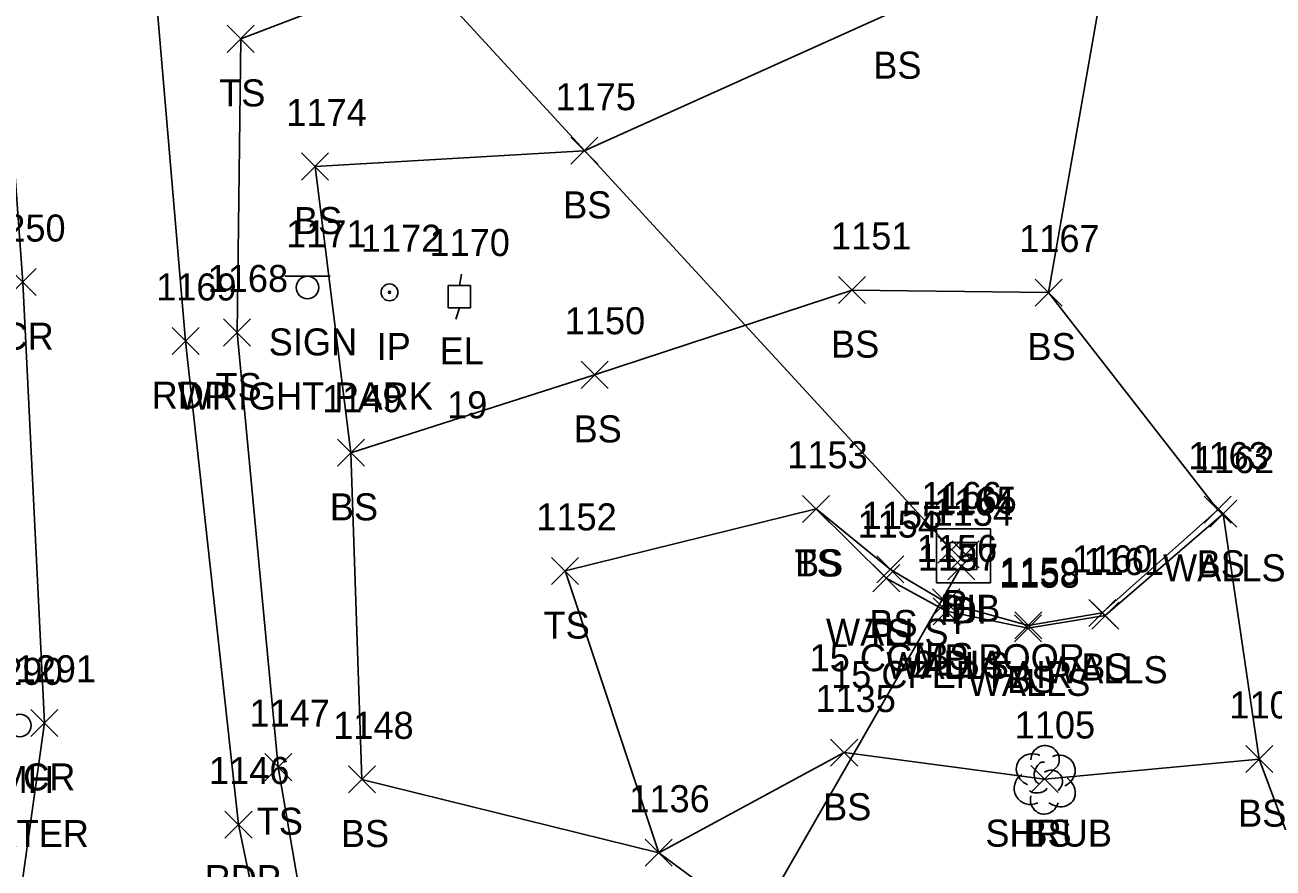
# Model space of a CAD drawing. Extents: x 1461855 to 1464118, y 556196 to 557441.
# Drawn here: x 1462417.3 to 1462509.6, y 556442 to 556504.3 of the extents above; entities that cross this region are included whole.
import ezdxf

# ---------------------------------------------------------------- set-up
doc = ezdxf.new("R2010")
doc.units = 0
for name, color, linetype in [('D_A', 7, 'Continuous'), ('D_C', 7, 'Continuous'), ('D_I', 7, 'Continuous'), ('D_TIC', 7, 'Continuous'), ('DCP', 7, 'Continuous'), ('DS', 7, 'Continuous'), ('L_A', 7, 'Continuous'), ('L_I', 7, 'Continuous'), ('L_TIC', 7, 'Continuous'), ('LELB', 7, 'Continuous'), ('LSH', 7, 'Continuous'), ('LSOGP', 7, 'Continuous'), ('LWS', 7, 'Continuous'), ('M_A', 7, 'Continuous'), ('M_I', 7, 'Continuous'), ('MPIR', 7, 'Continuous'), ('P_A', 7, 'Continuous'), ('P_I', 7, 'Continuous'), ('P_TIC', 7, 'Continuous'), ('PET', 7, 'Continuous'), ('PRC', 7, 'Continuous'), ('S_A', 7, 'Continuous'), ('S_C', 7, 'Continuous'), ('S_I', 7, 'Continuous'), ('SSGN', 7, 'Continuous'), ('U_A', 7, 'Continuous'), ('U_C', 7, 'Continuous'), ('U_I', 7, 'Continuous'), ('UEPT', 7, 'Continuous'), ('UUMH', 7, 'Continuous')]:
    doc.layers.add(name, color=color, linetype=linetype)

msp = doc.modelspace()

# ---------------------------------------------------------------- linework, layer by layer
at = {"layer": 'D_TIC'}
for points in [[(1462484.784, 556464.552), (1462486.784, 556466.552)], [(1462486.784, 556464.552), (1462484.784, 556466.552)], [(1462485.833, 556464.207), (1462487.833, 556466.207)], [(1462487.833, 556464.207), (1462485.833, 556466.207)], [(1462485.51, 556463.306), (1462487.51, 556465.306)], [(1462487.51, 556463.306), (1462485.51, 556465.306)]]:
    msp.add_lwpolyline(points, dxfattribs=at)
at = {"layer": 'DCP'}
for points in [[(1462485.784, 556465.552), (1462401.016, 556557.727)], [(1462451.827, 556403.885), (1462486.51, 556464.306)]]:
    msp.add_lwpolyline(points, dxfattribs=at)
at = {"layer": 'DS'}
for p, q in [((1462484.67, 556467.079), (1462488.67, 556467.079)), ((1462484.67, 556463.079), (1462484.67, 556467.079)), ((1462488.67, 556467.079), (1462488.67, 556463.079)), ((1462485.67, 556464.079), (1462485.67, 556466.079)), ((1462485.67, 556466.079), (1462487.67, 556466.079)), ((1462487.67, 556466.079), (1462487.67, 556464.079)), ((1462486.675, 556465.081), (1462486.675, 556465.081)), ((1462486.675, 556465.081), (1462486.675, 556465.081)), ((1462487.67, 556464.079), (1462485.67, 556464.079)), ((1462488.67, 556463.079), (1462484.67, 556463.079))]:
    msp.add_line(p, q, dxfattribs=at)
at = {"layer": 'L_TIC'}
for points in [[(1462432.214, 556502.32), (1462434.214, 556504.32)], [(1462434.214, 556502.32), (1462432.214, 556504.32)], [(1462457.622, 556494.039), (1462459.622, 556496.039)], [(1462459.622, 556494.039), (1462457.622, 556496.039)], [(1462437.718, 556492.877), (1462439.718, 556494.877)], [(1462439.718, 556492.877), (1462437.718, 556494.877)], [(1462477.434, 556483.742), (1462479.434, 556485.742)], [(1462479.434, 556483.742), (1462477.434, 556485.742)], [(1462491.963, 556483.557), (1462493.963, 556485.557)], [(1462493.963, 556483.557), (1462491.963, 556485.557)], [(1462431.945, 556480.601), (1462433.945, 556482.601)], [(1462433.945, 556480.601), (1462431.945, 556482.601)], [(1462458.394, 556477.473), (1462460.394, 556479.473)], [(1462460.394, 556477.473), (1462458.394, 556479.473)], [(1462440.368, 556471.708), (1462442.368, 556473.708)], [(1462442.368, 556471.708), (1462440.368, 556473.708)], [(1462440.368, 556471.708), (1462442.368, 556473.708)], [(1462442.368, 556471.708), (1462440.368, 556473.708)], [(1462474.768, 556467.56), (1462476.768, 556469.56)], [(1462476.768, 556467.56), (1462474.768, 556469.56)], [(1462474.768, 556467.56), (1462476.768, 556469.56)], [(1462476.768, 556467.56), (1462474.768, 556469.56)], [(1462504.472, 556467.494), (1462506.472, 556469.494)], [(1462506.472, 556467.494), (1462504.472, 556469.494)], [(1462504.882, 556467.202), (1462506.882, 556469.202)], [(1462506.882, 556467.202), (1462504.882, 556469.202)], [(1462456.204, 556462.965), (1462458.204, 556464.965)], [(1462458.204, 556462.965), (1462456.204, 556464.965)], [(1462480.271, 556463.082), (1462482.271, 556465.082)], [(1462482.271, 556463.082), (1462480.271, 556465.082)], [(1462479.956, 556462.433), (1462481.956, 556464.433)], [(1462481.956, 556462.433), (1462479.956, 556464.433)], [(1462479.956, 556462.433), (1462481.956, 556464.433)], [(1462481.956, 556462.433), (1462479.956, 556464.433)], [(1462484.391, 556460.638), (1462486.391, 556462.638)], [(1462486.391, 556460.638), (1462484.391, 556462.638)], [(1462484.417, 556459.986), (1462486.417, 556461.986)], [(1462486.417, 556459.986), (1462484.417, 556461.986)], [(1462495.939, 556459.865), (1462497.939, 556461.865)], [(1462497.939, 556459.865), (1462495.939, 556461.865)], [(1462490.459, 556458.944), (1462492.459, 556460.944)], [(1462492.459, 556458.944), (1462490.459, 556460.944)], [(1462496.158, 556459.665), (1462498.158, 556461.665)], [(1462498.158, 556459.665), (1462496.158, 556461.665)], [(1462490.442, 556458.729), (1462492.442, 556460.729)], [(1462492.442, 556458.729), (1462490.442, 556460.729)], [(1462476.846, 556449.533), (1462478.846, 556451.533)], [(1462478.846, 556449.533), (1462476.846, 556451.533)], [(1462507.542, 556449.057), (1462509.542, 556451.057)], [(1462509.542, 556449.057), (1462507.542, 556451.057)], [(1462434.991, 556448.457), (1462436.991, 556450.457)], [(1462436.991, 556448.457), (1462434.991, 556450.457)], [(1462441.185, 556447.55), (1462443.185, 556449.55)], [(1462443.185, 556447.55), (1462441.185, 556449.55)], [(1462441.185, 556447.55), (1462443.185, 556449.55)], [(1462443.185, 556447.55), (1462441.185, 556449.55)], [(1462491.661, 556447.578), (1462493.661, 556449.578)], [(1462493.661, 556447.578), (1462491.661, 556449.578)], [(1462463.138, 556442.125), (1462465.138, 556444.125)], [(1462465.138, 556442.125), (1462463.138, 556444.125)], [(1462463.138, 556442.125), (1462465.138, 556444.125)], [(1462465.138, 556442.125), (1462463.138, 556444.125)]]:
    msp.add_lwpolyline(points, dxfattribs=at)
at = {"layer": 'LELB'}
for points in [[(1462439.15, 556431.127), (1462435.991, 556449.457), (1462432.945, 556481.601), (1462433.214, 556503.32), (1462454.223, 556511.365), (1462474.435, 556520.417), (1462493.382, 556525.455)], [(1462442.185, 556448.55), (1462441.368, 556472.708), (1462438.718, 556493.877), (1462458.622, 556495.039), (1462481.557, 556505.37), (1462497.969, 556513.067)], [(1462441.368, 556472.708), (1462459.394, 556478.473), (1462478.434, 556484.742), (1462492.963, 556484.557)], [(1462511.588, 556441.871), (1462496.726, 556434.616), (1462482.019, 556429.925), (1462464.138, 556443.125), (1462457.204, 556463.965), (1462475.768, 556468.56), (1462480.956, 556463.433)], [(1462475.768, 556468.56), (1462481.271, 556464.082), (1462485.391, 556461.638), (1462491.459, 556459.944), (1462496.939, 556460.865), (1462505.472, 556468.494)], [(1462508.542, 556450.057), (1462492.661, 556448.578), (1462477.846, 556450.533), (1462464.138, 556443.125), (1462442.185, 556448.55)]]:
    msp.add_lwpolyline(points, dxfattribs=at)
at = {"layer": 'LSH'}
msp.add_line((1462492.661, 556448.578), (1462492.661, 556448.578), dxfattribs=at)
msp.add_line((1462492.661, 556448.578), (1462492.661, 556448.578), dxfattribs=at)
msp.add_arc((1462492.707, 556450.011), 1.047, 335.52715, 180.95627, dxfattribs=at)
for centre, major_axis, ratio, start_param, end_param in [((1462491.869, 556449.244), (1.21, -0.512), 0.895232, 1.570796, 4.712389), ((1462492.452, 556449.036), (-0.208, -0.792), 0.645439, 3.141593, 6.283185), ((1462493.702, 556449.161), (-1.141, -0.483), 0.949671, 1.570796, 4.712389), ((1462491.577, 556447.869), (0.584, -1.042), 0.959034, 3.141593, 6.283185), ((1462493.161, 556448.411), (-0.5, 0.667), 0.989748, 3.141593, 6.283185), ((1462492.202, 556447.827), (-0.625, -0.083), 0.423636, 0, 3.141593), ((1462493.661, 556447.744), (-1.09, 0.792), 0.841452, 1.570796, 4.712389), ((1462492.661, 556447.078), (0.265, 1.061), 0.942809, 1.570796, 4.712389)]:
    msp.add_ellipse(centre, major_axis=major_axis, ratio=ratio, start_param=start_param, end_param=end_param, dxfattribs=at)
at = {"layer": 'LSOGP'}
msp.add_lwpolyline([(1462563.174, 556376.777), (1462561.339, 556379.019), (1462559.886, 556380.724), (1462547.912, 556393.804), (1462536.148, 556406.17), (1462534.091, 556416.372), (1462526.144, 556425.112), (1462519.567, 556432.393), (1462517.78, 556434.532), (1462511.588, 556441.871), (1462508.542, 556450.057), (1462505.882, 556468.202), (1462505.472, 556468.494), (1462492.963, 556484.557), (1462497.969, 556513.067)], dxfattribs=at)
at = {"layer": 'LWS'}
msp.add_lwpolyline([(1462480.956, 556463.433), (1462485.417, 556460.986), (1462491.442, 556459.729), (1462497.158, 556460.665), (1462505.882, 556468.202)], dxfattribs=at)
at = {"layer": 'MPIR'}
for radius in [0.625, 0.0833]:
    msp.add_circle((1462444.222, 556484.572), radius, dxfattribs=at)
at = {"layer": 'P_TIC'}
for points in [[(1462416.096, 556484.328), (1462418.096, 556486.328)], [(1462418.096, 556484.328), (1462416.096, 556486.328)], [(1462428.146, 556479.97), (1462430.146, 556481.97)], [(1462430.146, 556479.97), (1462428.146, 556481.97)], [(1462417.694, 556451.734), (1462419.694, 556453.734)], [(1462419.694, 556451.734), (1462417.694, 556453.734)], [(1462432.054, 556444.214), (1462434.054, 556446.214)], [(1462434.054, 556444.214), (1462432.054, 556446.214)]]:
    msp.add_lwpolyline(points, dxfattribs=at)
at = {"layer": 'PET'}
msp.add_lwpolyline([(1462450.002, 556394.495), (1462444.864, 556401.11), (1462442.305, 556410.091), (1462435.592, 556433.018), (1462433.054, 556445.214), (1462429.146, 556480.97), (1462426.421, 556512.859), (1462424.327, 556541.511), (1462422.907, 556563.514), (1462420.115, 556594.818)], dxfattribs=at)
at = {"layer": 'PRC'}
msp.add_lwpolyline([(1462408.918, 556592.161), (1462412.204, 556557.563), (1462413.993, 556527.838), (1462417.096, 556485.328), (1462418.694, 556452.734), (1462415.654, 556430.869), (1462414.08, 556417.651)], dxfattribs=at)
at = {"layer": 'SSGN'}
for p, q in [((1462436.504, 556485.758), (1462439.838, 556485.758)), ((1462438.151, 556484.925), (1462438.151, 556484.925))]:
    msp.add_line(p, q, dxfattribs=at)
msp.add_circle((1462438.151, 556484.925), 0.833, dxfattribs=at)
at = {"layer": 'UEPT'}
for p, q in [((1462449.553, 556485.921), (1462449.386, 556485.088)), ((1462448.553, 556483.421), (1462448.553, 556485.088)), ((1462448.553, 556485.088), (1462450.22, 556485.088)), ((1462450.22, 556485.088), (1462450.22, 556483.421)), ((1462449.386, 556484.254), (1462449.386, 556484.254)), ((1462450.22, 556483.421), (1462448.553, 556483.421)), ((1462449.136, 556482.588), (1462449.386, 556483.421))]:
    msp.add_line(p, q, dxfattribs=at)
at = {"layer": 'UUMH'}
msp.add_line((1462417.712, 556452.544), (1462417.712, 556452.544), dxfattribs=at)
msp.add_circle((1462416.878, 556452.544), 0.833, dxfattribs=at)

# ---------------------------------------------------------------- texts
at = {"layer": 'D_A'}
for s, p in [('DIB', (1462484.936, 556460.207)), ('P', (1462485.162, 556460.552)), ('DI', (1462485.731, 556460.081)), ('P', (1462485.888, 556459.306))]:
    msp.add_text(s, height=2, dxfattribs=at).set_placement(p)
at = {"layer": 'D_C'}
for s, p in [('15 CGMP POOR', (1462475.288, 556456.552)), ('2 DIA', (1462482.951, 556456.081)), ('15 CPEP FAIR', (1462476.88, 556455.306))]:
    msp.add_text(s, height=2, dxfattribs=at).set_placement(p)
at = {"layer": 'D_I'}
for s, p in [('1166', (1462483.555, 556468.552)), ('1164', (1462484.502, 556468.081)), ('1165', (1462484.66, 556468.207)), ('1134', (1462484.384, 556467.306))]:
    msp.add_text(s, height=2, dxfattribs=at).set_placement(p)
at = {"layer": 'L_A'}
for s, p in [('BS', (1462479.998, 556500.37)), ('TS', (1462431.624, 556498.32)), ('BS', (1462457.063, 556490.039)), ('BS', (1462437.159, 556488.877)), ('BS', (1462476.875, 556479.742)), ('BS', (1462491.404, 556479.557)), ('TS', (1462431.355, 556476.601)), ('BS', (1462457.835, 556473.473)), ('BS', (1462439.809, 556467.708)), ('BS', (1462439.809, 556467.708)), ('TS', (1462474.177, 556463.56)), ('BS', (1462474.209, 556463.56)), ('BS', (1462503.913, 556463.494)), ('WALLS', (1462501.426, 556463.202)), ('TS', (1462455.613, 556458.965)), ('BS', (1462479.712, 556459.082)), ('WALLS', (1462476.499, 556458.433)), ('TS', (1462479.365, 556458.433)), ('BS', (1462483.832, 556456.638)), ('WALLS', (1462480.961, 556455.986)), ('WALLS', (1462492.701, 556455.665)), ('BS', (1462495.38, 556455.865)), ('WALLS', (1462486.986, 556454.729)), ('BS', (1462489.9, 556454.944)), ('BS', (1462476.287, 556445.533)), ('BS', (1462506.983, 556445.057)), ('TS', (1462434.4, 556444.457)), ('BS', (1462440.626, 556443.55)), ('BS', (1462440.626, 556443.55)), ('SHRUB', (1462488.29, 556443.578)), ('BS', (1462491.101, 556443.578))]:
    msp.add_text(s, height=2, dxfattribs=at).set_placement(p)
at = {"layer": 'L_I'}
for s, p in [('1175', (1462456.496, 556498.039)), ('1174', (1462436.592, 556496.877)), ('1151', (1462476.875, 556487.742)), ('1167', (1462490.789, 556487.557)), ('1168', (1462430.772, 556484.601)), ('1150', (1462457.181, 556481.473)), ('1149', (1462439.235, 556475.708)), ('1149', (1462439.235, 556475.708)), ('1153', (1462473.642, 556471.56)), ('1153', (1462473.642, 556471.56)), ('1163', (1462503.299, 556471.494)), ('1162', (1462503.709, 556471.202)), ('1152', (1462455.078, 556466.965)), ('1154', (1462478.83, 556466.433)), ('1154', (1462478.83, 556466.433)), ('1155', (1462479.145, 556467.082)), ('1156', (1462483.21, 556464.638)), ('1157', (1462483.291, 556463.986)), ('1160', (1462494.679, 556463.865)), ('1161', (1462495.552, 556463.665)), ('1158', (1462489.316, 556462.729)), ('1159', (1462489.325, 556462.944)), ('1135', (1462475.72, 556453.533)), ('1147', (1462433.865, 556452.457)), ('1104', (1462506.337, 556453.057)), ('1148', (1462440.059, 556451.55)), ('1148', (1462440.059, 556451.55)), ('1105', (1462490.456, 556451.578)), ('1105', (1462490.456, 556451.578)), ('1136', (1462461.957, 556446.125)), ('1136', (1462461.957, 556446.125))]:
    msp.add_text(s, height=2, dxfattribs=at).set_placement(p)
at = {"layer": 'M_A'}
msp.add_text('IP', height=2, dxfattribs=at).set_placement((1462443.269, 556479.572))
at = {"layer": 'M_I'}
msp.add_text('1172', height=2, dxfattribs=at).set_placement((1462442.096, 556487.572))
at = {"layer": 'P_A'}
for s, p in [('CR', (1462415.529, 556480.328)), ('RDP', (1462426.634, 556475.97)), ('CR', (1462417.127, 556447.734)), ('RDP', (1462430.542, 556440.214))]:
    msp.add_text(s, height=2, dxfattribs=at).set_placement(p)
at = {"layer": 'P_I'}
for s, p in [('1250', (1462414.317, 556488.328)), ('1169', (1462426.965, 556483.97)), ('1291', (1462416.568, 556455.734)), ('1146', (1462430.873, 556448.214))]:
    msp.add_text(s, height=2, dxfattribs=at).set_placement(p)
at = {"layer": 'S_A'}
msp.add_text('SIGN', height=2, dxfattribs=at).set_placement((1462435.289, 556479.905))
at = {"layer": 'S_C'}
msp.add_text('WRIGHT PARK', height=2, dxfattribs=at).set_placement((1462428.557, 556475.905))
at = {"layer": 'S_I'}
msp.add_text('1171', height=2, dxfattribs=at).set_placement((1462436.573, 556487.905))
at = {"layer": 'U_A'}
for s, p in [('EL', (1462447.922, 556479.254)), ('MH', (1462415.241, 556447.544))]:
    msp.add_text(s, height=2, dxfattribs=at).set_placement(p)
at = {"layer": 'U_C'}
for s, p in [('19', (1462448.481, 556475.254)), ('WATER', (1462412.335, 556443.544))]:
    msp.add_text(s, height=2, dxfattribs=at).set_placement(p)
at = {"layer": 'U_I'}
for s, p in [('1170', (1462447.174, 556487.254)), ('1290', (1462414.099, 556455.544))]:
    msp.add_text(s, height=2, dxfattribs=at).set_placement(p)

doc.saveas('drawing.dxf')
